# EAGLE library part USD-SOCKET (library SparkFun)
microSD Socket Push-push type uSD socket. Schematic element and footprint production proven. Spark Fun Electronics SKU : PType-microSD. tDoc lines correctly indicate media card edge positions when inserting (unlocked, locked, depressed).
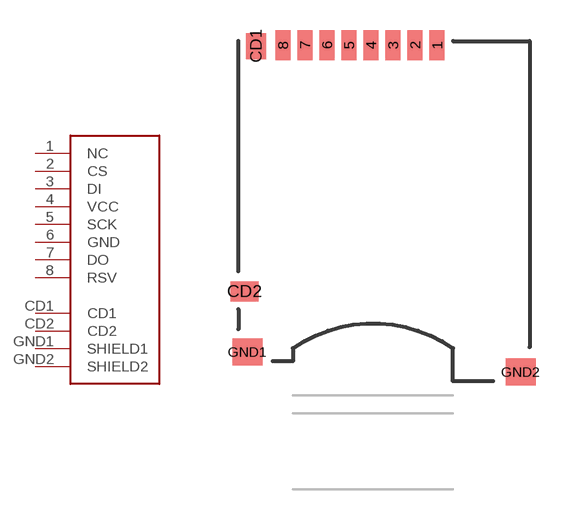
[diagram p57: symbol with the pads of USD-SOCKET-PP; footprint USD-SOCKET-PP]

Designator prefix -

## USD-SOCKETUSD  [USD-SOCKET-PP]
1  NC
2  CS
3  DI
4  VCC
5  SCK
6  GND
7  DO
8  RSV
CD1  CD1
CD2  CD2
GND1  SHIELD1
GND2  SHIELD2

## Footprint USD-SOCKET-PP (pad centres in mm)
smd 0.75 x 1.5: 1 3.2,16.8; 2 2.1,16.8; 3 1,16.8; 4 -0.1,16.8; 5 -1.2,16.8; 6 -2.3,16.8; 7 -3.4,16.8; 8 -4.5,16.8
smd 1 x 1.3: CD1 -5.85,16.75
smd 1.4 x 1: CD2 -6.425,4.5
smd 1.5 x 1.35: GND1 -6.275,1.475; GND2 7.375,0.475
